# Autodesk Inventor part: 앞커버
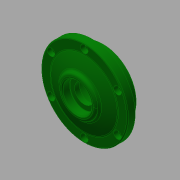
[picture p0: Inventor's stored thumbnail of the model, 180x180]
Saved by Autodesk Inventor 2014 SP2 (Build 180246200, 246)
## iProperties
Created: 2016-05
Part Number: 앞커버
Document SubType Name: Modeling
Designer: mduedu
Density: 2.71 g/cm^3
Material: 알루미늄 6061
Appearance: 진녹색
Author: mduedu
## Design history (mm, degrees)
sketch "스케치1"
  geometry: C1 r 35 at (0, 0); C2 r 45 at (0, 0); 1 further point
  constraints: 2 centre point, 2 coincident
  dimensions: "d33" = 90 diameter of C2; "d34" = 70 diameter of C1
extrude "돌출1" new body sketch "스케치1" distance "d0" = 8; taper "d1" = 0 deg
extrude "돌출2" join sketch "스케치1" distance "d2" = 8; taper "d3" = 0 deg; dims "d35" = 12, "d36" = 0
sketch "스케치5"
  geometry: L1 (-45, 8)-(45, 8) reference; L2 (0, 0)-(0, 15); L3 (-45, 0)-(45, 0) reference; L4 (35, 8)-(0, 8); A1 r 91 centre (0, -76) between (35, 8) and (0, 15)
  constraints: 4 end point, 3 point on line, 2 point on circle, 1 centre point, 1 midpoint, 1 perpendicular
  dimensions: "d37" = 35 distance from line of L2 L4.start; "d39" = 7 distance from line of L1 L2.end
revolve "회전2" sketch "스케치5" stored, may be unused: angle "d40" = 90 deg
node "작업 평면1"
sketch "스케치6"
  geometry: C1 r 20 at (0, 0); 1 further point
  constraints: 1 centre point, 1 coincident
  dimensions: "d42" = 40 diameter of C1
extrude "돌출4" join sketch "스케치6" stored distance "d43" = 10; taper "d44" = 0 deg
sketch "스케치4"
  geometry: L1 (0, -12)-(0, 16); L2 (-20, -12)-(-20, 0); L3 (-20, 0)-(-15, 0); L4 (-15, 0)-(-15, 3); L5 (-15, 3)-(-10, 3); L6 (-10, 3)-(-10, 8); L7 (-10, 8)-(-15, 8); L8 (-15, 8)-(-15, 16); L9 (35, -12)-(-35, -12) reference; L10 (-20, 16)-(20, 16) reference; 1 further point
  constraints: 16 end point, 6 parallel, 3 point on line, 2 midpoint, 1 perpendicular, 1 vertical
  dimensions: "d15" = 40 diameter of L2 L1; "d16" = 30 diameter of L8 L1; "d18" = 12 distance of L2.start L2.end; "d19" = 3 distance of L3.end L4.end; "d20" = 30 diameter of L4 L1; "d21" = 20 diameter of L6 L1; "d45" = 8 distance of L7.end L8.end
revolve "회전1" sketch "스케치4" stored, may be unused: angle "d22" = 90 deg
fillet "모깎기2" dims "d23" = 3
fillet "모깎기3" dims "d24" = 0.3
chamfer "모따기2" distance "d46" = 1; stored, may be unused: second distance "d47" = 2, angle "d48" = 45 deg
fillet "모깎기4" dims "d49" = 3
fillet "모깎기5" dims "d50" = 3
fillet "모깎기6" dims "d51" = 1
sketch "스케치7" dims "d52" = 80
  geometry: C1 r 35.595 at (0, 0) reference; C2 r 44 at (0, 0) reference; 7 further points
  constraints: 2 vertical alignment, 1 coincident, 9 other
  dimensions: "d55" = 360 deg dimension on C1.centre point (0, 40) (derived)
sketch "스케치8"
  geometry: 6 further points
  constraints: 6 other
hole "구멍2" sketch "스케치8" at (-34.641, 20), (-34.641, -20), (0, -40), (34.641, -20), (34.641, 20), (0, 40) diameter "d57" = 4.5; stored, may be unused: countersink angle "d61" = 90 deg, drill point angle "d63" = 0 deg; dims "d58" = 6, "d59" = 8, "d60" = 4.6, "d62" = 8
node "솔리드1"
other parameters: "d41" = 8
